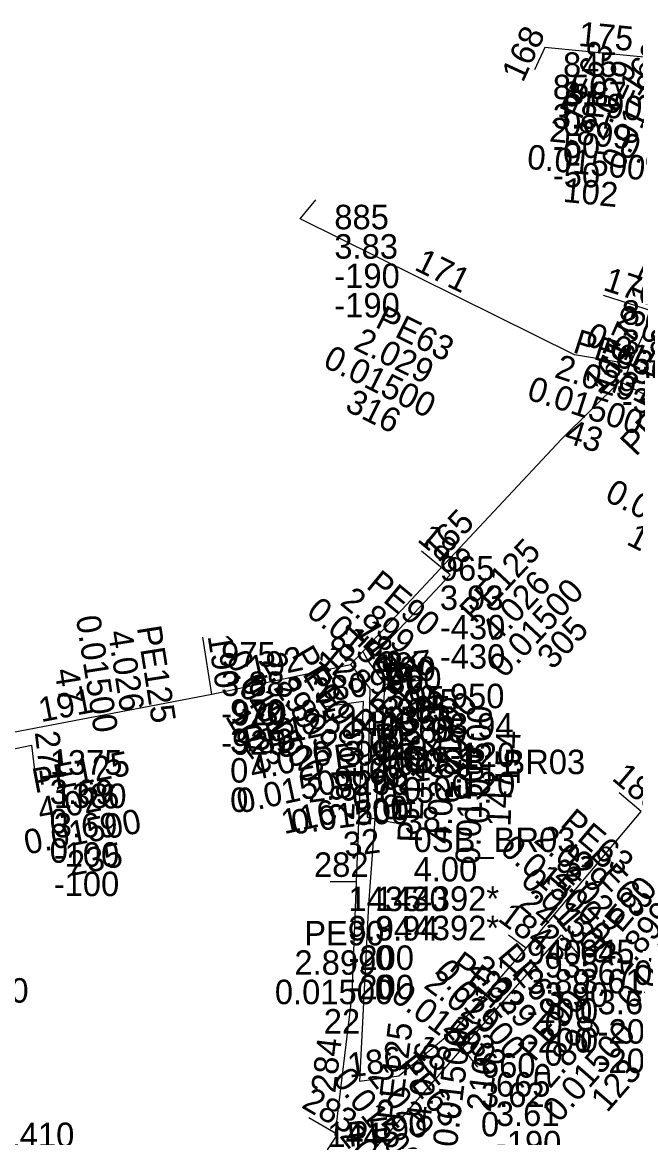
# Model space of a CAD drawing. Extents: x 607463 to 609569, y 4065893 to 4067650.
# Drawn here: x 608262 to 608763, y 4066739 to 4067650 of the extents above; entities that cross this region are included whole.
import ezdxf

# ---------------------------------------------------------------- set-up
doc = ezdxf.new("R2010")
doc.units = 0
for name, color, linetype in [('BR', 7, 'Continuous'), ('GW_NATT', 7, 'Continuous'), ('GW_NODETX', 7, 'Continuous'), ('GW_PATT', 7, 'Continuous'), ('PE125', 7, 'Continuous'), ('PE63', 7, 'Continuous'), ('PE90', 7, 'Continuous'), ('ST06', 7, 'Continuous')]:
    doc.layers.add(name, color=color, linetype=linetype)

msp = doc.modelspace()

# ---------------------------------------------------------------- linework, layer by layer
at = {"layer": 'PE125'}
for p, q in [((608758.38, 4067370.75), (608777.62, 4067413.75)), ((608755.5, 4067362.5), (608758.38, 4067370.75)), ((608750.06, 4067356.75), (608755.5, 4067362.5)), ((608416.44, 4067101), (608409.06, 4067147.75)), ((608539.81, 4067136), (608529.94, 4067125.5)), ((608416.44, 4067101), (608185.94, 4067056.75)), ((608534.81, 4066948), (608540.56, 4067095.25))]:
    msp.add_line(p, q, dxfattribs=at)
for points in [[(608750.06, 4067356.75), (608702.38, 4067309.5), (608539.81, 4067136)], [(608994.19, 4067235.25), (608949.31, 4067253.25), (608943.43, 4067256.07), (608929.5, 4067261.75), (608750.06, 4067356.75)], [(608529.94, 4067125.5), (608529.75, 4067125.25), (608416.44, 4067101)], [(608519.25, 4066741.5), (608517.25, 4066740.75), (608531.25, 4066855.75), (608534.81, 4066948)], [(608437.81, 4066607.25), (608466.5, 4066660.75), (608519.25, 4066741.5)]]:
    msp.add_lwpolyline(points, dxfattribs=at)
at = {"layer": 'PE63'}
for p, q in [((608688.62, 4067629.5), (608680.25, 4067611.25)), ((608777.62, 4067413.75), (608736.62, 4067427)), ((608557.88, 4067109.5), (608596.06, 4067113.75)), ((608268.94, 4067059.5), (608272.25, 4067032.25)), ((608767.5, 4067005.5), (608749.44, 4067020.75)), ((608673.5, 4066893.75), (608659.06, 4066904.5)), ((608702.44, 4066904.75), (608716.88, 4066887.75)), ((608621.5, 4066812), (608633.69, 4066796.5))]:
    msp.add_line(p, q, dxfattribs=at)
for points in [[(608758.38, 4067370.75), (608712.94, 4067378.5), (608488.81, 4067489.5), (608501.62, 4067505)], [(608755.5, 4067362.5), (608908.06, 4067285.5), (608917.5, 4067301.25)]]:
    msp.add_lwpolyline(points, dxfattribs=at)
at = {"layer": 'PE90'}
for p, q in [((608789.75, 4067619.5), (608688.62, 4067629.5)), ((608539.81, 4067136), (608544.62, 4067127.75)), ((608540.56, 4067095.25), (608509.19, 4067091)), ((608673.5, 4066893.75), (608767.5, 4067005.5)), ((608534.81, 4066948), (608513.19, 4066948)), ((608621.5, 4066812), (608702.44, 4066904.75)), ((608519.25, 4066741.5), (608495.88, 4066755.25))]:
    msp.add_line(p, q, dxfattribs=at)
for points in [[(608544.62, 4067127.75), (608611.25, 4067198.75), (608587.88, 4067218)], [(608544.62, 4067127.75), (608557.88, 4067109.5), (608557.88, 4067109.5)], [(608557.88, 4067109.5), (608544.44, 4066929.5), (608537.19, 4066785), (608569.25, 4066789.5), (608616.75, 4066828.75), (608673.5, 4066893.75)], [(608140.12, 4066984.75), (608132.81, 4067021.25), (608130.12, 4067030.75), (608268.94, 4067059.5)], [(608540.56, 4066678), (608544.56, 4066723.75), (608621.5, 4066812)]]:
    msp.add_lwpolyline(points, dxfattribs=at)
at = {"layer": 'ST06'}
msp.add_lwpolyline([(608529.94, 4067125.5), (608545.62, 4067105.75), (608543.44, 4067000.75), (608566.44, 4066996.25)], dxfattribs=at)

# ---------------------------------------------------------------- texts
at = {"layer": 'BR'}
msp.add_text('0SB_BR03', height=20, dxfattribs=at).set_placement((608589.39, 4067035.9))
at = {"layer": 'GW_NATT'}
for s, p in [('3.87 ', (608703.62, 4067581.5)), ('3.87 ', (608695.25, 4067563.25)), ('0 ', (608703.62, 4067557.5)), ('-50 ', (608695.25, 4067539.25)), ('0 ', (608703.62, 4067533.5)), ('-50 ', (608695.25, 4067515.25)), ('3.83 ', (608516.62, 4067457)), ('-190 ', (608516.62, 4067433)), ('-190 ', (608516.62, 4067409)), ('3.87 ', (608751.62, 4067379)), ('-300 ', (608751.62, 4067355)), ('-300 ', (608751.62, 4067331)), ('3.93 ', (608602.88, 4067170)), ('-430 ', (608602.88, 4067146)), ('-430 ', (608602.88, 4067122)), ('3.88 ', (608424.06, 4067099.75)), ('3.95 ', (608554.82, 4067088)), ('3.95 ', (608559.62, 4067079.75)), ('-920 ', (608424.06, 4067075.75)), ('3.96 ', (608544.94, 4067077.45)), ('0 ', (608554.82, 4067064)), ('3.95 ', (608572.88, 4067061.5)), ('3.94 ', (608611.06, 4067065.75)), ('-920 ', (608424.06, 4067051.75)), ('3.89 ', (608431.44, 4067053)), ('0 ', (608544.94, 4067053.45)), ('0 ', (608559.62, 4067055.75)), ('3.94 ', (608524.19, 4067043)), ('3.94 ', (608555.56, 4067047.25)), ('0 ', (608554.82, 4067040)), ('0 ', (608572.88, 4067037.5)), ('-120 ', (608611.06, 4067041.75)), ('0 ', (608431.44, 4067029)), ('0 ', (608544.94, 4067029.45)), ('0 ', (608559.62, 4067031.75)), ('-200 ', (608524.19, 4067019)), ('0 ', (608555.56, 4067023.25)), ('-120 ', (608611.06, 4067017.75)), ('3.69 ', (608283.94, 4067011.5)), ('0 ', (608572.88, 4067013.5)), ('0 ', (608431.44, 4067005)), ('0 ', (608555.56, 4066999.25)), ('-200 ', (608524.19, 4066995)), ('0 ', (608283.94, 4066987.5)), ('3.69 ', (608287.25, 4066984.25)), ('0 ', (608283.94, 4066963.5)), ('-100 ', (608287.25, 4066960.25)), ('4.00 ', (608581.44, 4066948.25)), ('-100 ', (608287.25, 4066936.25)), ('4392* ', (608581.44, 4066924.25)), ('3.94 ', (608528.19, 4066900)), ('3.94 ', (608549.84, 4066899.99)), ('4392* ', (608581.44, 4066900.25)), ('-200 ', (608528.19, 4066876)), ('0 ', (608549.84, 4066875.99)), ('-200 ', (608528.19, 4066852)), ('0 ', (608549.84, 4066851.99)), ('3.89 ', (608674.06, 4066856.5)), ('3.61 ', (608717.44, 4066856.75)), ('3.90 ', (608688.5, 4066845.75)), ('0 ', (608717.44, 4066832.75)), ('3.61 ', (608731.88, 4066839.75)), ('-200 ', (608674.06, 4066832.5)), ('0 ', (608688.5, 4066821.75)), ('-200 ', (608731.88, 4066815.75)), ('-200 ', (608674.06, 4066808.5)), ('0 ', (608717.44, 4066808.75)), ('0 ', (608688.5, 4066797.75)), ('-200 ', (608731.88, 4066791.75)), ('3.62 ', (608636.51, 4066763.96)), ('3.61 ', (608648.69, 4066748.5)), ('0 ', (608636.51, 4066739.96)), ('-190 ', (608648.69, 4066724.5))]:
    msp.add_text(s, height=20, dxfattribs=at).set_placement(p)
at = {"layer": 'GW_NODETX'}
for s, p in [('845', (608703.62, 4067605.5)), ('850', (608695.25, 4067587.25)), ('885', (608516.62, 4067481)), ('870', (608751.62, 4067403)), ('965', (608602.88, 4067194)), ('975', (608424.06, 4067123.75)), ('920', (608554.82, 4067112)), ('980', (608544.94, 4067101.45)), ('960', (608559.62, 4067103.75)), ('950', (608611.06, 4067089.75)), ('945', (608572.88, 4067085.5)), ('970', (608431.44, 4067077)), ('1365', (608555.56, 4067071.25)), ('1425', (608524.19, 4067067)), ('1375', (608283.94, 4067035.5)), ('1380', (608287.25, 4067008.25)), ('0SB_BR03', (608581.44, 4066972.25)), ('1435', (608528.19, 4066924)), ('1430', (608549.84, 4066923.99)), ('940', (608674.06, 4066880.5)), ('645', (608717.44, 4066880.75)), ('935', (608688.5, 4066869.75)), ('670', (608731.88, 4066863.75)), ('1400', (608207.19, 4066849.25)), ('660', (608636.51, 4066787.96)), ('665', (608648.69, 4066772.5)), ('1410', (608244.56, 4066731.25)), ('1445', (608510.88, 4066731.25))]:
    msp.add_text(s, height=20, dxfattribs=at).set_placement(p)
at = {"layer": 'GW_PATT'}
for s, rotation, p in [('168', 65.35, (608670.79, 4067600.23)), ('175', 354.35, (608715.7, 4067630.84)), ('PE63', 65.35, (608718.35, 4067569.6)), ('169', 57.4, (608765.14, 4067588.44)), ('2.029', 65.35, (608736.83, 4067552.32)), ('0.01500', 65.35, (608751.97, 4067527.77)), ('PE90', 354.35, (608702.23, 4067575.9)), ('2.899', 354.35, (608691.9, 4067552.81)), ('0.01500', 336.96, (608747.77, 4067542.77)), ('0.01500', 354.35, (608673.62, 4067530.5)), ('102', 354.35, (608703.1, 4067503.46)), ('171', 333.65, (608581.14, 4067448.24)), ('174', 64.49, (608774.83, 4067417.19)), ('170', 342.09, (608735.52, 4067431.56)), ('PE63', 333.65, (608549.12, 4067401.6)), ('173', 65.88, (608754.54, 4067371.98)), ('2.029', 334.36, (608745.05, 4067402.54)), ('0.01500', 334.36, (608720.24, 4067387.83)), ('2.029', 333.65, (608531.3, 4067383.65)), ('PE63', 342.09, (608710.69, 4067380.74)), ('177', 70.79, (608745.26, 4067345.28)), ('0.01500', 333.65, (608506.31, 4067369.24)), ('166', 46.6, (608733.38, 4067344.94)), ('2.029', 342.09, (608695.69, 4067360.36)), ('31', 334.36, (608745.92, 4067348.88)), ('PE125', 46.6, (608763.08, 4067294.83)), ('0.01500', 342.09, (608673.09, 4067342.44)), ('316', 333.65, (608524.34, 4067333.53)), ('43', 342.09, (608703.77, 4067307.3)), ('0.01500', 333.22, (608736.73, 4067259.96)), ('165', 46.86, (608601.77, 4067207.97)), ('188', 320.53, (608583.58, 4067226.72)), ('189', 333.22, (608754.48, 4067224.11)), ('PE125', 46.86, (608631.69, 4067158.01)), ('PE90', 320.53, (608541.8, 4067188.58)), ('4.026', 46.86, (608649.2, 4067141.6)), ('0.01500', 46.86, (608655.78, 4067113.51)), ('2.899', 320.53, (608520.37, 4067175.14)), ('0.01500', 320.53, (608492.76, 4067166.78)), ('0.01500', 278.96, (608305.25, 4067164.11)), ('305', 46.86, (608695.17, 4067120.45)), ('PE125', 278.96, (608355.15, 4067155.78)), ('181', 46.76, (608515.52, 4067116.01)), ('182', 300.26, (608533.58, 4067154.62)), ('4.026', 278.96, (608331.45, 4067152.04)), ('190', 278.96, (608412.96, 4067148.71)), ('189', 305.98, (608540.39, 4067140.4)), ('0.01500', 300.26, (608427.62, 4067129.86)), ('192', 12.08, (608448.79, 4067112.01)), ('2.899', 300.26, (608456.42, 4067128.13)), ('PE90', 300.26, (608481.18, 4067133.31)), ('128', 320.53, (608502.21, 4067127.91)), ('PE125', 46.76, (608545.35, 4067065.99)), ('187', 6.35, (608552.67, 4067112.95)), ('47', 278.96, (608287.77, 4067120.86)), ('PE90', 305.98, (608490.37, 4067113.97)), ('280', 7.71, (608500.56, 4067093.87)), ('0.01500', 305.98, (608437.43, 4067105.19)), ('2.899', 305.98, (608466.25, 4067106.34)), ('4.026', 46.76, (608562.83, 4067049.54)), ('191', 10.87, (608276.86, 4067078.28)), ('0.01500', 46.76, (608569.36, 4067021.45)), ('0.01500', 88.81, (608643.34, 4066995.18)), ('10', 300.26, (608427.05, 4067083.22)), ('PE125', 12.08, (608444.86, 4067053.91)), ('PE63', 6.35, (608550.92, 4067056.4)), ('193', 88.81, (608540.03, 4067029.34)), ('6.217', 88.81, (608619.68, 4067011.68)), ('271', 276.93, (608271.67, 4067070.18)), ('23', 305.98, (608441.51, 4067058.72)), ('4.026', 12.08, (608449.88, 4067030.44)), ('PE90', 7.71, (608500.14, 4067037.3)), ('14', 46.76, (608614.24, 4067034.14)), ('154', 88.81, (608668, 4067026.67)), ('PE125', 10.87, (608271.71, 4067020.27)), ('2.029', 6.35, (608545.62, 4067031.67)), ('PE125', 87.76, (608588.09, 4066979.63)), ('6"', 88.81, (608596.19, 4067036.17)), ('0.01500', 87.76, (608635.43, 4066961.77)), ('4.026', 87.76, (608612.07, 4066978.69)), ('0.01500', 12.08, (608439.26, 4067003.62)), ('2.899', 7.71, (608495.44, 4067012.44)), ('281', 87.76, (608532.75, 4066997.8)), ('0.01500', 6.35, (608532.37, 4067006.04)), ('147', 87.76, (608660.66, 4066992.8)), ('183', 319.83, (608742.71, 4067031.66)), ('4.026', 10.87, (608276.23, 4066996.7)), ('0.01500', 7.71, (608482.81, 4066986.51)), ('116', 12.08, (608475.57, 4066986.85)), ('38', 6.35, (608574.78, 4066986.62)), ('PE63', 319.83, (608700.47, 4066994.04)), ('0.01500', 10.87, (608265.04, 4066970.11)), ('32', 7.71, (608525.66, 4066968.1)), ('2.029', 319.83, (608678.88, 4066980.86)), ('0.01500', 319.83, (608651.17, 4066972.84)), ('235', 10.87, (608301, 4066952.57)), ('185', 49.93, (608701.99, 4066933.83)), ('PE63', 314.22, (608719.13, 4066964.04)), ('2.029', 314.22, (608696.35, 4066953.04)), ('0.01500', 314.22, (608668, 4066947.77)), ('PE90', 49.93, (608739.7, 4066891.66)), ('24', 319.83, (608666.25, 4066928.7)), ('184', 323.33, (608649.42, 4066916.67)), ('133', 310.34, (608697.17, 4066917.13)), ('2.899', 49.93, (608752.91, 4066870.09)), ('0.01500', 49.93, (608760.98, 4066842.4)), ('23', 314.22, (608678.69, 4066902.37)), ('PE63', 323.33, (608609.56, 4066876.53)), ('PE63', 310.34, (608649.31, 4066886.98)), ('0.01500', 310.34, (608597.18, 4066874.2)), ('2.029', 310.34, (608625.83, 4066877.54)), ('131', 48.89, (608643.17, 4066842.92)), ('2.029', 323.33, (608588.81, 4066862.06)), ('0.01500', 323.33, (608561.64, 4066852.36)), ('PE90', 48.89, (608680.11, 4066800.07)), ('22', 310.34, (608604.78, 4066828.18)), ('2.899', 48.89, (608692.93, 4066778.27)), ('PE125', 83.06, (608571.04, 4066752.26)), ('0.01500', 83.06, (608616.75, 4066730.58)), ('132', 308.18, (608615.9, 4066825.59)), ('0.01500', 48.89, (608700.49, 4066750.43)), ('284', 83.06, (608517.38, 4066774.91)), ('18', 323.33, (608579.39, 4066809.22)), ('186', 7.99, (608528.9, 4066787.88)), ('PE63', 308.18, (608566.94, 4066797.26)), ('4.026', 83.06, (608594.86, 4066749.36)), ('210', 83.06, (608644.44, 4066759.44)), ('123', 48.89, (608739.62, 4066758.76)), ('0.01500', 308.18, (608514.37, 4066786.46)), ('2.029', 308.18, (608543.13, 4066788.72)), ('283', 329.53, (608488.9, 4066763.99)), ('PE90', 7.99, (608528.76, 4066731.31)), ('20', 308.18, (608520.23, 4066740.18))]:
    msp.add_text(s, height=20, rotation=rotation, dxfattribs=at).set_placement(p)
for s, p in [('282', (608500, 4066952)), ('PE90', (608492, 4066896)), ('2.899', (608484, 4066872)), ('0.01500', (608468, 4066848)), ('22', (608508, 4066824))]:
    msp.add_text(s, height=20, dxfattribs=at).set_placement(p)

doc.saveas('drawing.dxf')
